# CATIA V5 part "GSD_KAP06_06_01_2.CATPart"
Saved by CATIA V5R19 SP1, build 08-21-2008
Part number: GSD_OFFSET_03
Definition: Beispielmodell für Funktionen Übergang, Füllen und Offset.
Description: CATIA V5 Flächenmodellierung  Copyright (c) 2009 Maik Hertha IT Consultants
Bounding box of the stored display mesh (mm): x 0 to 49.234, y -0.206 to 47.42, z 0 to 65.132
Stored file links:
  \GSD_BUCH_UEBUNG\GSD_KAP06_06_01_2.CATPart
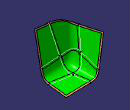
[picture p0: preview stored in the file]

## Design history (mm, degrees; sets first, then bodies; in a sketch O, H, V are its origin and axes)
AxisSystem1 "Absolute Axis System": origin (0, 0, 0), X (1, 0, 0), Y (0, 1, 0), Z (0, 0, 1)
Set1 "Planes.1"
  Plane1: type Equation, A 0, B 1, C 0, Length 0
  Plane2: type Equation, A 0, B 0, C 1, Length 0
  Plane3: type Equation, A 1, B 0, C 0, Length 0
Set2 "Skizzen.1"
  Sketch1 on Plane1, origin (0, 0, 0), H (-1, 0, 0), V (0, 0, 1)
    line L1 (-40.7892, 13.7277) -> (-49.2341, 65.1316)
    line L2 (-49.2341, 65.1316) -> (-29.5293, 63.051)
    line L3 (-29.5293, 63.051) -> (-14.1082, 15.4412)
    line L4 (-14.1082, 15.4412) -> (-40.7892, 13.7277)
  Sketch2 on Plane3, origin (0, 0, 0), H (0, 1, 0), V (0, 0, 1)
    line L1 (16.0881, 21.2572) -> (13.3955, 53.2011)
    line L2 (13.3955, 53.2011) -> (47.42, 60.6669)
    line L3 (47.42, 60.6669) -> (41.3005, 12.9347)
    line L4 (41.3005, 12.9347) -> (16.0881, 21.2572)
  Sketch3 on Plane2, origin (0, 0, 0), H (1, 0, 0), V (0, 1, 0)
    line L1 (12.7396, 17.2746) -> (9.9246, 38.9377)
    line L2 (9.9246, 38.9377) -> (44.561, 39.7944)
    line L3 (44.561, 39.7944) -> (41.746, 12.379)
    line L4 (41.746, 12.379) -> (12.7396, 17.2746)
Set3 "Basisflaechen.1"
  Split1: ToCut Plane1, Cutting Sketch1
  Split2: ToCut Plane3, Cutting Sketch2
  Split3: ToCut Plane2, Cutting Sketch3
Set4 "Blends"
  Boundary1: Boundary edge of Split1
  Boundary2: Boundary edge of Split3
  Boundary3: Boundary edge of Split1
  Boundary4: Boundary edge of Split2
  Boundary5: Boundary edge of Split2
  Boundary6: Boundary edge of Split3
  Blend1: StartLimit {blendlimit Support Split3, Curve Boundary2}, EndLimit {blendlimit Support Split1, Curve Boundary1}
  Blend2: StartLimit {blendlimit Support Split1, Curve Boundary3}, EndLimit {blendlimit Support Split2, Curve Boundary4}
  Blend3: StartLimit {blendlimit Support Split2, Curve Boundary5}, EndLimit {blendlimit Support Split3, Curve Boundary6}
Set5 "Fill"
  Extract1: ExtractElem edge of Blend2
  Extract2: ExtractElem edge of Blend3
  Extract3: ExtractElem edge of Blend1
  Fill1: Boundary ({fillboundary Support Blend1, BoundaryWire Extract3}; {fillboundary Support Blend2, BoundaryWire Extract1}; {fillboundary Support Blend3, BoundaryWire Extract2})
Set6 "Offset"
  Join1: Elements (Split3; Blend1; Blend3; Split1; Fill1; Split2; Blend2)
  Offset1: Length 3, Offset Join1
Body1 (main body)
